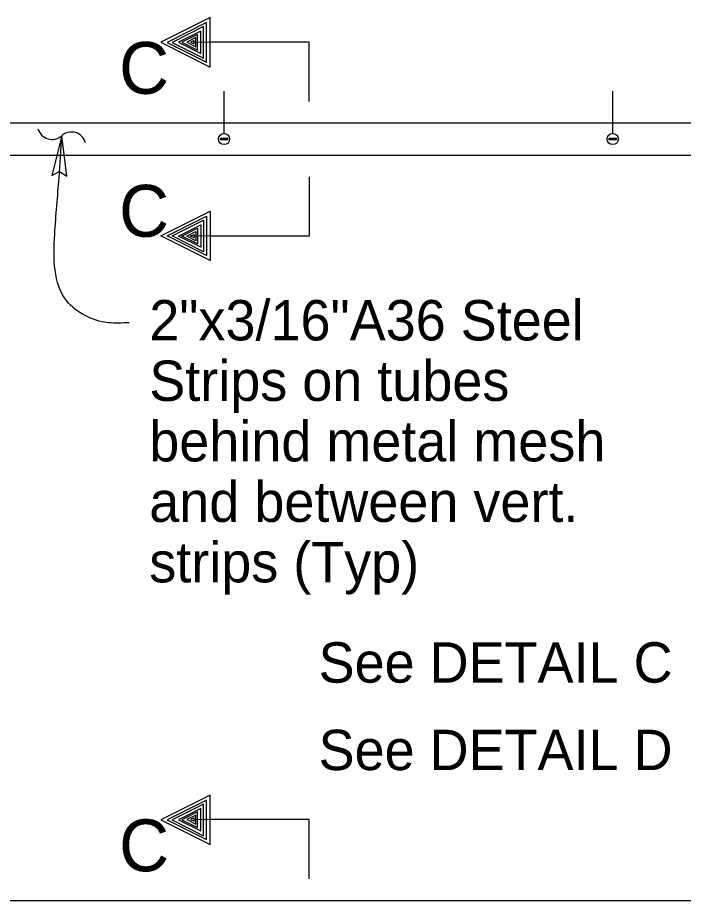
# Model space of a CAD drawing. Extents: x 0 to 2.83, y -0.03 to 1.83.
# Drawn here: x 0.2734 to 0.4875, y 1.2159 to 1.4997 of the extents above; entities that cross this region are included whole.
import ezdxf

# ---------------------------------------------------------------- set-up
doc = ezdxf.new("R2010")
doc.units = 0
for name, color, linetype in [('52', 7, 'Continuous'), ('54', 7, 'Continuous'), ('55', 7, 'Continuous'), ('57', 7, 'Continuous')]:
    doc.layers.add(name, color=color, linetype=linetype)

msp = doc.modelspace()

# ---------------------------------------------------------------- linework, layer by layer
at = {"layer": '52'}
for p, q in [((0.1991976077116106, 1.4658686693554), (0.6054476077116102, 1.4658686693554)), ((0.3410696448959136, 1.4608909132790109), (0.33857557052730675, 1.4608909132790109)), ((0.3410696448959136, 1.4604297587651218), (0.33857557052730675, 1.4604297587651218)), ((0.4660696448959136, 1.4608909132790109), (0.46357557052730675, 1.4608909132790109)), ((0.4660696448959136, 1.4604297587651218), (0.46357557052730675, 1.4604297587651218)), ((0.1991976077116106, 1.4554520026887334), (0.6054476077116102, 1.4554520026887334)), ((0.1991976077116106, 1.2158686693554), (0.6054476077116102, 1.2158686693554))]:
    msp.add_line(p, q, dxfattribs=at)
for centre in [(0.3398226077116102, 1.4606603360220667), (0.4648226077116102, 1.4606603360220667)]:
    msp.add_circle(centre, 0.0017903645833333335, dxfattribs=at)
for centre, start, end in [((0.3398226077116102, 1.4606603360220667), 169.52431830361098, 190.47568169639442), ((0.3398226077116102, 1.4606603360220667), 349.5243183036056, 10.475681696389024), ((0.4648226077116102, 1.4606603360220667), 169.52431830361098, 190.47568169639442), ((0.4648226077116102, 1.4606603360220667), 349.5243183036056, 10.475681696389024)]:
    msp.add_arc(centre, 0.0012681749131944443, start, end, dxfattribs=at)
at = {"layer": '54'}
msp.add_lwpolyline([(0.28762855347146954, 1.4617341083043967), (0.28443679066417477, 1.4489186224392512), (0.2869024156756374, 1.4502737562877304), (0.28921171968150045, 1.448766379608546)], close=True, dxfattribs=at)
at = {"layer": '55'}
for p, q in [((0.3398226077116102, 1.4624507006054), (0.3398226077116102, 1.476080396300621)), ((0.4648226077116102, 1.4624507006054), (0.4648226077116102, 1.476080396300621))]:
    msp.add_line(p, q, dxfattribs=at)
for points in [[(0.3671312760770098, 1.4727470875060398), (0.3671312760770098, 1.4918552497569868), (0.3353812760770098, 1.4918552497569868), (0.3353812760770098, 1.4997052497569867), (0.31950627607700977, 1.4917719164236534), (0.3353812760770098, 1.4838302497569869), (0.3353812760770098, 1.49173858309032), (0.3341979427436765, 1.4918552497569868), (0.3341979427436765, 1.4980969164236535), (0.32149794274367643, 1.4917469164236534), (0.3341979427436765, 1.4853969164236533), (0.3341979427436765, 1.49173858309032), (0.3332479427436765, 1.4918552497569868), (0.3332479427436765, 1.4968135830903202), (0.32308960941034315, 1.4917302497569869), (0.3332479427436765, 1.4866552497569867), (0.3332479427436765, 1.49173858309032), (0.33229794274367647, 1.4918552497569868), (0.33229794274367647, 1.4953719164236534), (0.3251479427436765, 1.4917885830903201), (0.33229794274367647, 1.4882219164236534), (0.33229794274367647, 1.49173858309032), (0.3313062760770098, 1.4918552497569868), (0.3313062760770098, 1.4943302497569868), (0.32627294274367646, 1.4917969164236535), (0.3313062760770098, 1.4892885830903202), (0.3313062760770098, 1.49173858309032), (0.3307312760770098, 1.4918552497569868), (0.3307312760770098, 1.4932802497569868), (0.32779794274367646, 1.49181358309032), (0.3307312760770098, 1.4903552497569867), (0.3307312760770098, 1.49173858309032), (0.33016460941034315, 1.4918552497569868), (0.33016460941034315, 1.49238858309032), (0.32907294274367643, 1.4918552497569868), (0.33016460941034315, 1.4913052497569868), (0.33016460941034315, 1.49173858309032)], [(0.3671312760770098, 1.4485214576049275), (0.3671312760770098, 1.4294132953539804), (0.3353812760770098, 1.4294132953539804), (0.3353812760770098, 1.4215632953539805), (0.31950627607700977, 1.4294966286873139), (0.3353812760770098, 1.4374382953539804), (0.3353812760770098, 1.4295299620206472), (0.3341979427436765, 1.4294132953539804), (0.3341979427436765, 1.4231716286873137), (0.32149794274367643, 1.4295216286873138), (0.3341979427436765, 1.4358716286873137), (0.3341979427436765, 1.4295299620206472), (0.3332479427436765, 1.4294132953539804), (0.3332479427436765, 1.424454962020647), (0.32308960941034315, 1.4295382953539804), (0.3332479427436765, 1.4346132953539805), (0.3332479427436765, 1.4295299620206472), (0.33229794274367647, 1.4294132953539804), (0.33229794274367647, 1.4258966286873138), (0.3251479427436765, 1.429479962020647), (0.33229794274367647, 1.4330466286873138), (0.33229794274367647, 1.4295299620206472), (0.3313062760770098, 1.4294132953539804), (0.3313062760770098, 1.4269382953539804), (0.32627294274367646, 1.4294716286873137), (0.3313062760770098, 1.431979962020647), (0.3313062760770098, 1.4295299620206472), (0.3307312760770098, 1.4294132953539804), (0.3307312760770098, 1.4279882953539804), (0.32779794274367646, 1.4294549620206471), (0.3307312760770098, 1.4309132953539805), (0.3307312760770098, 1.4295299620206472), (0.33016460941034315, 1.4294132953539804), (0.33016460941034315, 1.4288799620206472), (0.32907294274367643, 1.4294132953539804), (0.33016460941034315, 1.4299632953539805), (0.33016460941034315, 1.4295299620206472)], [(0.3671312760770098, 1.2227470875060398), (0.3671312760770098, 1.2418552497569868), (0.3353812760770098, 1.2418552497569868), (0.3353812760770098, 1.2497052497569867), (0.31950627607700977, 1.2417719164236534), (0.3353812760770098, 1.2338302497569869), (0.3353812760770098, 1.24173858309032), (0.3341979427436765, 1.2418552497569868), (0.3341979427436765, 1.2480969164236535), (0.32149794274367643, 1.2417469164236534), (0.3341979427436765, 1.2353969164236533), (0.3341979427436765, 1.24173858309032), (0.3332479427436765, 1.2418552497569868), (0.3332479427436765, 1.24681358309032), (0.32308960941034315, 1.2417302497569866), (0.3332479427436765, 1.2366552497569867), (0.3332479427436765, 1.24173858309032), (0.33229794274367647, 1.2418552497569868), (0.33229794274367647, 1.2453719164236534), (0.3251479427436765, 1.2417885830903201), (0.33229794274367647, 1.2382219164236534), (0.33229794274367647, 1.24173858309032), (0.3313062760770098, 1.2418552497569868), (0.3313062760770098, 1.2443302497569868), (0.32627294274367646, 1.2417969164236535), (0.3313062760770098, 1.2392885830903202), (0.3313062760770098, 1.24173858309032), (0.3307312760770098, 1.2418552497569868), (0.3307312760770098, 1.2432802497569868), (0.32779794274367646, 1.24181358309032), (0.3307312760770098, 1.2403552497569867), (0.3307312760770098, 1.24173858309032), (0.33016460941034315, 1.2418552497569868), (0.33016460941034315, 1.24238858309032), (0.32907294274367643, 1.2418552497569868), (0.33016460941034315, 1.2413052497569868), (0.33016460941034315, 1.24173858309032)]]:
    msp.add_lwpolyline(points, dxfattribs=at)
for centre, radius, start, end in [((0.2845053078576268, 1.4652429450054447), 0.004697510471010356, 195.266484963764, 311.67255440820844), ((0.2907517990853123, 1.458225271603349), 0.004697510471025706, 15.266484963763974, 131.6725544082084)]:
    msp.add_arc(centre, radius, start, end, dxfattribs=at)
msp.add_spline([(0.3092976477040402, 1.4016172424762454), (0.30252528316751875, 1.4016172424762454), (0.28921396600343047, 1.4086086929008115), (0.28536068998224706, 1.429976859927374), (0.2867618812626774, 1.4481923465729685), (0.28762855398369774, 1.4617341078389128)], degree=3, dxfattribs=at)

# ---------------------------------------------------------------- texts
at = {"layer": '57'}
for s, height, p in [('C', 0.01667, (0.306054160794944, 1.4752148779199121)), ('C', 0.01667, (0.306054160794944, 1.429253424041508)), ('2"x3/16"A36 Steel', 0.012980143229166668, (0.31577464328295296, 1.3959131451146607)), ('Strips on tubes', 0.012980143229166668, (0.31577464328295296, 1.3764632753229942)), ('behind metal mesh', 0.012980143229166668, (0.31577464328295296, 1.3570134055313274)), ('and between vert.', 0.012980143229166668, (0.31577464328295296, 1.3375635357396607)), ('strips (Typ)', 0.012980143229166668, (0.31577464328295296, 1.3181136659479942)), ('See DETAIL C', 0.012980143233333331, (0.3702155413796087, 1.2858731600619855)), ('See DETAIL D', 0.012980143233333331, (0.3702155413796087, 1.2577465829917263)), ('C', 0.01667, (0.306054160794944, 1.2252148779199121))]:
    msp.add_text(s, height=height, dxfattribs=at).set_placement(p)

doc.saveas('drawing.dxf')
